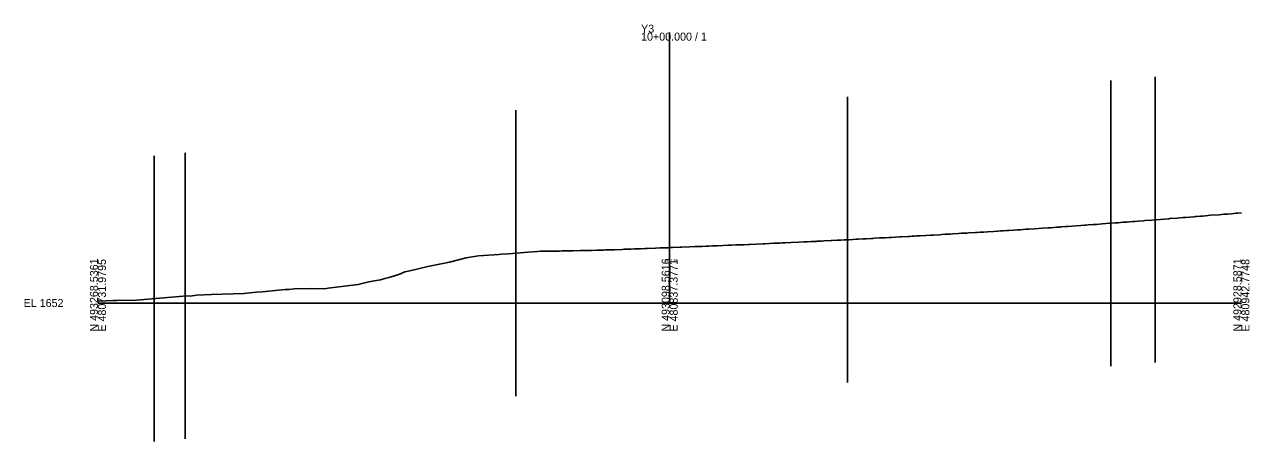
# Model space of a CAD drawing. Extents: x -26 to 481018, y -48 to 493233.
# Drawn here: x -25.7 to 402.8, y -48.5 to 97.5 of the extents above; entities that cross this region are included whole.
import ezdxf

# ---------------------------------------------------------------- set-up
doc = ezdxf.new("R2010")
doc.units = 0
for name, color, linetype in [('Exist Cross Section Cell', 7, 'Continuous'), ('Exist XS Center Line Elevation Label', 7, 'Continuous'), ('Exist XS Ground Line', 7, 'Continuous'), ('Scratch_Level_5', 7, 'Continuous')]:
    doc.layers.add(name, color=color, linetype=linetype)

msp = doc.modelspace()

# ---------------------------------------------------------------- linework, layer by layer
at = {"layer": 'Exist Cross Section Cell'}
for p, q in [((200, 0), (200, 94.63)), ((0, 0), (200, 0)), ((200, 0), (400, 0))]:
    msp.add_line(p, q, dxfattribs=at)
at = {"layer": 'Exist XS Ground Line'}
for p, q in [((380.46, 29.98), (381.97, 30.09)), ((381.97, 30.09), (383.41, 30.21)), ((383.41, 30.21), (383.79, 30.24)), ((383.79, 30.24), (384.44, 30.3)), ((384.44, 30.3), (385.66, 30.39)), ((385.66, 30.39), (386.39, 30.45)), ((386.39, 30.45), (387.49, 30.53)), ((387.49, 30.53), (389.33, 30.69)), ((389.33, 30.69), (392.23, 30.91)), ((392.23, 30.91), (393.9, 31.05)), ((393.9, 31.05), (394.7, 31.11)), ((394.7, 31.11), (395.19, 31.15)), ((395.19, 31.15), (396.54, 31.26)), ((396.54, 31.26), (398.14, 31.39)), ((398.14, 31.39), (398.73, 31.44)), ((398.73, 31.44), (400, 31.54)), ((322.73, 25.67), (324.56, 25.79)), ((324.56, 25.79), (325.73, 25.86)), ((325.73, 25.86), (327.57, 25.98)), ((327.57, 25.98), (330.46, 26.17)), ((330.46, 26.17), (332.33, 26.3)), ((332.33, 26.3), (333.41, 26.37)), ((333.41, 26.37), (335.35, 26.51)), ((335.35, 26.51), (336.53, 26.59)), ((336.53, 26.59), (336.89, 26.62)), ((336.89, 26.62), (338.44, 26.74)), ((338.44, 26.74), (339.29, 26.8)), ((339.29, 26.8), (342.21, 27.01)), ((342.21, 27.01), (343.84, 27.13)), ((343.84, 27.13), (345.17, 27.23)), ((345.17, 27.23), (345.66, 27.27)), ((345.66, 27.27), (346.46, 27.32)), ((346.46, 27.32), (348.15, 27.44)), ((348.15, 27.44), (349.32, 27.53)), ((349.32, 27.53), (351.31, 27.68)), ((351.31, 27.68), (353.99, 27.89)), ((353.99, 27.89), (355.9, 28.04)), ((355.9, 28.04), (356.54, 28.08)), ((356.54, 28.08), (356.94, 28.11)), ((356.94, 28.11), (358.56, 28.24)), ((358.56, 28.24), (359.89, 28.34)), ((359.89, 28.34), (360.71, 28.4)), ((360.71, 28.4), (362, 28.5)), ((362, 28.5), (362.81, 28.57)), ((362.81, 28.57), (363.84, 28.65)), ((363.84, 28.65), (365.76, 28.81)), ((365.76, 28.81), (366.19, 28.84)), ((366.19, 28.84), (368.71, 29.04)), ((368.71, 29.04), (370.22, 29.16)), ((370.22, 29.16), (371.67, 29.27)), ((371.67, 29.27), (372.93, 29.37)), ((372.93, 29.37), (374.61, 29.51)), ((374.61, 29.51), (375.01, 29.54)), ((375.01, 29.54), (377.53, 29.74)), ((377.53, 29.74), (379.64, 29.91)), ((379.64, 29.91), (380.46, 29.98)), ((247.73, 21.42), (248.08, 21.43)), ((248.08, 21.43), (249.46, 21.5)), ((249.46, 21.5), (251.27, 21.58)), ((251.27, 21.58), (251.61, 21.6)), ((251.61, 21.6), (253.08, 21.67)), ((253.08, 21.67), (253.99, 21.72)), ((253.99, 21.72), (256.47, 21.84)), ((256.47, 21.84), (256.9, 21.86)), ((256.9, 21.86), (258.56, 21.95)), ((258.56, 21.95), (259.9, 22.01)), ((259.9, 22.01), (261.06, 22.07)), ((261.06, 22.07), (262.38, 22.15)), ((262.38, 22.15), (262.84, 22.17)), ((262.84, 22.17), (265.38, 22.31)), ((265.38, 22.31), (265.94, 22.34)), ((265.94, 22.34), (267.72, 22.44)), ((267.72, 22.44), (268.7, 22.5)), ((268.7, 22.5), (270.58, 22.6)), ((270.58, 22.6), (271.05, 22.63)), ((271.05, 22.63), (271.68, 22.66)), ((271.68, 22.66), (273.41, 22.76)), ((273.41, 22.76), (274.89, 22.84)), ((274.89, 22.84), (275.39, 22.86)), ((275.39, 22.86), (276.8, 22.94)), ((276.8, 22.94), (277.5, 22.98)), ((277.5, 22.98), (280.47, 23.14)), ((280.47, 23.14), (281.01, 23.17)), ((281.01, 23.17), (283.44, 23.3)), ((283.44, 23.3), (283.94, 23.33)), ((283.94, 23.33), (284.78, 23.38)), ((284.78, 23.38), (285.67, 23.42)), ((285.67, 23.42), (286.39, 23.46)), ((286.39, 23.46), (287.6, 23.53)), ((287.6, 23.53), (289.62, 23.64)), ((289.62, 23.64), (291.24, 23.74)), ((291.24, 23.74), (292.21, 23.79)), ((292.21, 23.79), (294.39, 23.92)), ((294.39, 23.92), (295.15, 23.96)), ((295.15, 23.96), (296.43, 24.04)), ((296.43, 24.04), (298.12, 24.14)), ((298.12, 24.14), (299.06, 24.2)), ((299.06, 24.2), (301.08, 24.32)), ((301.08, 24.32), (302.12, 24.39)), ((302.12, 24.39), (304.07, 24.5)), ((304.07, 24.5), (304.59, 24.53)), ((304.59, 24.53), (306.94, 24.67)), ((306.94, 24.67), (307.55, 24.71)), ((307.55, 24.71), (308.47, 24.77)), ((308.47, 24.77), (309.88, 24.85)), ((309.88, 24.85), (311.19, 24.94)), ((311.19, 24.94), (313.26, 25.07)), ((313.26, 25.07), (314.83, 25.17)), ((314.83, 25.17), (315.78, 25.23)), ((315.78, 25.23), (316.64, 25.29)), ((316.64, 25.29), (317.96, 25.37)), ((317.96, 25.37), (318.69, 25.41)), ((318.69, 25.41), (320.29, 25.52)), ((320.29, 25.52), (321.65, 25.6)), ((321.65, 25.6), (322.73, 25.67)), ((141.22, 17.04), (143.63, 17.25)), ((143.63, 17.25), (147.8, 17.6)), ((147.8, 17.6), (150.34, 17.82)), ((150.34, 17.82), (153.71, 18.08)), ((153.71, 18.08), (154.76, 18.09)), ((154.76, 18.09), (155.85, 18.09)), ((155.85, 18.09), (156.9, 18.13)), ((156.9, 18.13), (158.67, 18.15)), ((158.67, 18.15), (159.92, 18.17)), ((159.92, 18.17), (160.49, 18.18)), ((160.49, 18.18), (161.42, 18.2)), ((161.42, 18.2), (162.37, 18.21)), ((162.37, 18.21), (162.86, 18.22)), ((162.86, 18.22), (164.15, 18.24)), ((164.15, 18.24), (165.73, 18.28)), ((165.73, 18.28), (166.27, 18.29)), ((166.27, 18.29), (168.76, 18.34)), ((168.76, 18.34), (169.59, 18.35)), ((169.59, 18.35), (170.96, 18.38)), ((170.96, 18.38), (171.66, 18.4)), ((171.66, 18.4), (172.7, 18.43)), ((172.7, 18.43), (174.54, 18.48)), ((174.54, 18.48), (174.97, 18.49)), ((174.97, 18.49), (175.7, 18.51)), ((175.7, 18.51), (176.89, 18.55)), ((176.89, 18.55), (177.58, 18.57)), ((177.58, 18.57), (180.65, 18.67)), ((180.65, 18.67), (183.42, 18.77)), ((183.42, 18.77), (184.09, 18.79)), ((184.09, 18.79), (185.15, 18.84)), ((185.15, 18.84), (186.37, 18.89)), ((186.37, 18.89), (187.7, 18.93)), ((187.7, 18.93), (189.54, 19.01)), ((189.54, 19.01), (189.9, 19.02)), ((189.9, 19.02), (191.32, 19.07)), ((191.32, 19.07), (192.18, 19.1)), ((192.18, 19.1), (195.1, 19.21)), ((195.1, 19.21), (196.83, 19.26)), ((196.83, 19.26), (198.07, 19.31)), ((198.07, 19.31), (199.44, 19.36)), ((199.44, 19.36), (200, 19.38)), ((200, 19.38), (200.45, 19.4)), ((200.45, 19.4), (201.04, 19.42)), ((201.04, 19.42), (203.69, 19.52)), ((203.69, 19.52), (204.2, 19.54)), ((204.2, 19.54), (206.98, 19.65)), ((206.98, 19.65), (208.95, 19.73)), ((208.95, 19.73), (209.96, 19.77)), ((209.96, 19.77), (211.34, 19.81)), ((211.34, 19.81), (212.73, 19.88)), ((212.73, 19.88), (213.1, 19.89)), ((213.1, 19.89), (213.7, 19.92)), ((213.7, 19.92), (214.93, 19.96)), ((214.93, 19.96), (215.71, 20)), ((215.71, 20), (216.77, 20.04)), ((216.77, 20.04), (218.71, 20.12)), ((218.71, 20.12), (220.45, 20.19)), ((220.45, 20.19), (221.64, 20.24)), ((221.64, 20.24), (223.12, 20.31)), ((223.12, 20.31), (224.58, 20.37)), ((224.58, 20.37), (225.86, 20.42)), ((225.86, 20.42), (227.54, 20.5)), ((227.54, 20.5), (227.94, 20.52)), ((227.94, 20.52), (230.43, 20.63)), ((230.43, 20.63), (232.69, 20.73)), ((232.69, 20.73), (233.35, 20.76)), ((233.35, 20.76), (234.94, 20.83)), ((234.94, 20.83), (236.36, 20.89)), ((236.36, 20.89), (236.76, 20.91)), ((236.76, 20.91), (237.38, 20.94)), ((237.38, 20.94), (238.59, 20.99)), ((238.59, 20.99), (239.33, 21.03)), ((239.33, 21.03), (240.42, 21.08)), ((240.42, 21.08), (242.4, 21.17)), ((242.4, 21.17), (245.17, 21.3)), ((245.17, 21.3), (246.92, 21.38)), ((246.92, 21.38), (247.73, 21.42)), ((115.45, 12.82), (119.5, 13.57)), ((119.5, 13.57), (122.97, 14.3)), ((122.97, 14.3), (128.87, 15.83)), ((128.87, 15.83), (133.07, 16.56)), ((133.07, 16.56), (140.2, 16.95)), ((140.2, 16.95), (141.22, 17.04)), ((100.33, 8.56), (101.73, 8.96)), ((101.73, 8.96), (103.76, 9.56)), ((103.76, 9.56), (105.86, 10.26)), ((105.86, 10.26), (107.39, 10.86)), ((107.39, 10.86), (107.97, 11.02)), ((107.97, 11.02), (109.05, 11.3)), ((109.05, 11.3), (115.45, 12.82)), ((57.41, 3.95), (65.55, 4.68)), ((65.55, 4.68), (66.78, 4.78)), ((66.78, 4.78), (68.71, 4.94)), ((68.71, 4.94), (74.54, 5.1)), ((74.54, 5.1), (79.26, 5.02)), ((79.26, 5.02), (80.49, 5.22)), ((80.49, 5.22), (82.39, 5.47)), ((82.39, 5.47), (91.03, 6.5)), ((91.03, 6.5), (94.8, 7.41)), ((94.8, 7.41), (96.71, 7.72)), ((96.71, 7.72), (98.87, 8.1)), ((98.87, 8.1), (100.33, 8.56)), ((0, 0.62), (5.16, 0.86)), ((5.16, 0.86), (5.82, 0.87)), ((5.82, 0.87), (6.62, 0.9)), ((6.62, 0.9), (13.46, 1)), ((13.46, 1), (25.73, 2.05)), ((25.73, 2.05), (31.05, 2.56)), ((31.05, 2.56), (32.28, 2.44)), ((32.28, 2.44), (34.52, 2.79)), ((34.52, 2.79), (39.7, 2.98)), ((39.7, 2.98), (51.04, 3.38)), ((51.04, 3.38), (54.22, 3.68)), ((54.22, 3.68), (55.45, 3.79)), ((55.45, 3.79), (57.41, 3.95))]:
    msp.add_line(p, q, dxfattribs=at)
at = {"layer": 'Scratch_Level_5'}
for p, q in [((354.29, 77.91), (354.29, -22.09)), ((369.82, 79.13), (369.82, -20.87)), ((262.2, 72.14), (262.2, -27.86)), ((146.22, 67.46), (146.22, -32.54)), ((19.69, 51.53), (19.69, -48.47)), ((30.48, 52.51), (30.48, -47.49))]:
    msp.add_line(p, q, dxfattribs=at)

# ---------------------------------------------------------------- texts
at = {"layer": 'Exist Cross Section Cell'}
for s, p in [('Y3', (190, 94.63)), ('10+00.000 / 1', (190, 91.83)), ('EL 1652', (-26, -1.4))]:
    msp.add_text(s, height=2.8, dxfattribs=at).set_placement(p)
for s, p in [('N 493268.5361', (0, -10)), ('E 480731.9795', (2.8, -10)), ('N 493098.5616', (200, -10)), ('E 480837.3771', (202.8, -10)), ('N 492928.5871', (400, -10)), ('E 480942.7748', (402.8, -10))]:
    msp.add_text(s, height=2.8, rotation=90, dxfattribs=at).set_placement(p)
at = {"layer": 'Exist XS Center Line Elevation Label'}
msp.add_text('1671.38', height=0.9, dxfattribs=at).set_placement((198.16, 14.48))

doc.saveas('drawing.dxf')
